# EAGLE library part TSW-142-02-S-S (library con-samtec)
THROUGH-HOLE .025" SQ POST HEADER Source: Samtec TSW.pdf
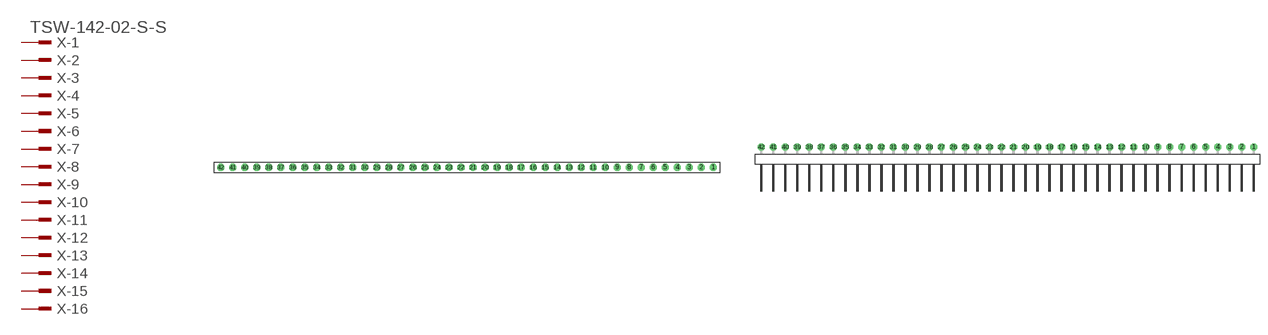
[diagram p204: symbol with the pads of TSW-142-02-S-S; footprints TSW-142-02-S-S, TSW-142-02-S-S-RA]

Designator prefix X; gates -1=MPINV -2=MPIN -3=MPIN -4=MPIN -5=MPIN -6=MPIN -7=MPIN -8=MPIN -9=MPIN -10=MPIN -11=MPIN -12=MPIN -13=MPIN -14=MPIN -15=MPIN -16=MPIN -17=MPIN -18=MPIN -19=MPIN -20=MPIN -21=MPIN -22=MPIN -23=MPIN -24=MPIN -25=MPIN -26=MPIN -27=MPIN -28=MPIN -29=MPIN -30=MPIN -31=MPIN -32=MPIN -33=MPIN -34=MPIN -35=MPIN -36=MPIN -37=MPIN -38=MPIN -39=MPIN -40=MPIN -41=MPIN -42=MPIN

## TSW-142-02-S-S (OC_FARNELL: unknown; OC_NEWARK: unknown)  [TSW-142-02-S-S]
1  -1:1  pas
2  -2:1  pas
3  -3:1  pas
4  -4:1  pas
5  -5:1  pas
6  -6:1  pas
7  -7:1  pas
8  -8:1  pas
9  -9:1  pas
10  -10:1  pas
11  -11:1  pas
12  -12:1  pas
13  -13:1  pas
14  -14:1  pas
15  -15:1  pas
16  -16:1  pas
17  -17:1  pas
18  -18:1  pas
19  -19:1  pas
20  -20:1  pas
21  -21:1  pas
22  -22:1  pas
23  -23:1  pas
24  -24:1  pas
25  -25:1  pas
26  -26:1  pas
27  -27:1  pas
28  -28:1  pas
29  -29:1  pas
30  -30:1  pas
31  -31:1  pas
32  -32:1  pas
33  -33:1  pas
34  -34:1  pas
35  -35:1  pas
36  -36:1  pas
37  -37:1  pas
38  -38:1  pas
39  -39:1  pas
40  -40:1  pas
41  -41:1  pas
42  -42:1  pas

## TSW-142-02-S-S-RA (OC_FARNELL: unknown; OC_NEWARK: unknown)  [TSW-142-02-S-S-RA]
Pads as for TSW-142-02-S-S

## Footprint TSW-142-02-S-S (pad centres in mm)
THROUGH-HOLE .025" SQ POST HEADER Source: Samtec TSW.pdf
drill 1 pad 1.5 octagon: 1 52.07,0; 2 49.53,0; 3 46.99,0; 4 44.45,0; 5 41.91,0; 6 39.37,0; 7 36.83,0; 8 34.29,0; 9 31.75,0; 10 29.21,0; 11 26.67,0; 12 24.13,0; 13 21.59,0; 14 19.05,0; 15 16.51,0; 16 13.97,0; 17 11.43,0; 18 8.89,0; 19 6.35,0; 20 3.81,0; 21 1.27,0; 22 -1.27,0; 23 -3.81,0; 24 -6.35,0; 25 -8.89,0; 26 -11.43,0; 27 -13.97,0; 28 -16.51,0; 29 -19.05,0; 30 -21.59,0; 31 -24.13,0; 32 -26.67,0; 33 -29.21,0; 34 -31.75,0; 35 -34.29,0; 36 -36.83,0; 37 -39.37,0; 38 -41.91,0; 39 -44.45,0; 40 -46.99,0; 41 -49.53,0; 42 -52.07,0

## Footprint TSW-142-02-S-S-RA (pad centres in mm)
THROUGH-HOLE .025" SQ POST HEADER Source: Samtec TSW.pdf
drill 1 pad 1.5 octagon: 1 52.07,1.524; 2 49.53,1.524; 3 46.99,1.524; 4 44.45,1.524; 5 41.91,1.524; 6 39.37,1.524; 7 36.83,1.524; 8 34.29,1.524; 9 31.75,1.524; 10 29.21,1.524; 11 26.67,1.524; 12 24.13,1.524; 13 21.59,1.524; 14 19.05,1.524; 15 16.51,1.524; 16 13.97,1.524; 17 11.43,1.524; 18 8.89,1.524; 19 6.35,1.524; 20 3.81,1.524; 21 1.27,1.524; 22 -1.27,1.524; 23 -3.81,1.524; 24 -6.35,1.524; 25 -8.89,1.524; 26 -11.43,1.524; 27 -13.97,1.524; 28 -16.51,1.524; 29 -19.05,1.524; 30 -21.59,1.524; 31 -24.13,1.524; 32 -26.67,1.524; 33 -29.21,1.524; 34 -31.75,1.524; 35 -34.29,1.524; 36 -36.83,1.524; 37 -39.37,1.524; 38 -41.91,1.524; 39 -44.45,1.524; 40 -46.99,1.524; 41 -49.53,1.524; 42 -52.07,1.524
